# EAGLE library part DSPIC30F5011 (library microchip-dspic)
dsPIC General DSP with CAN and I2S ports
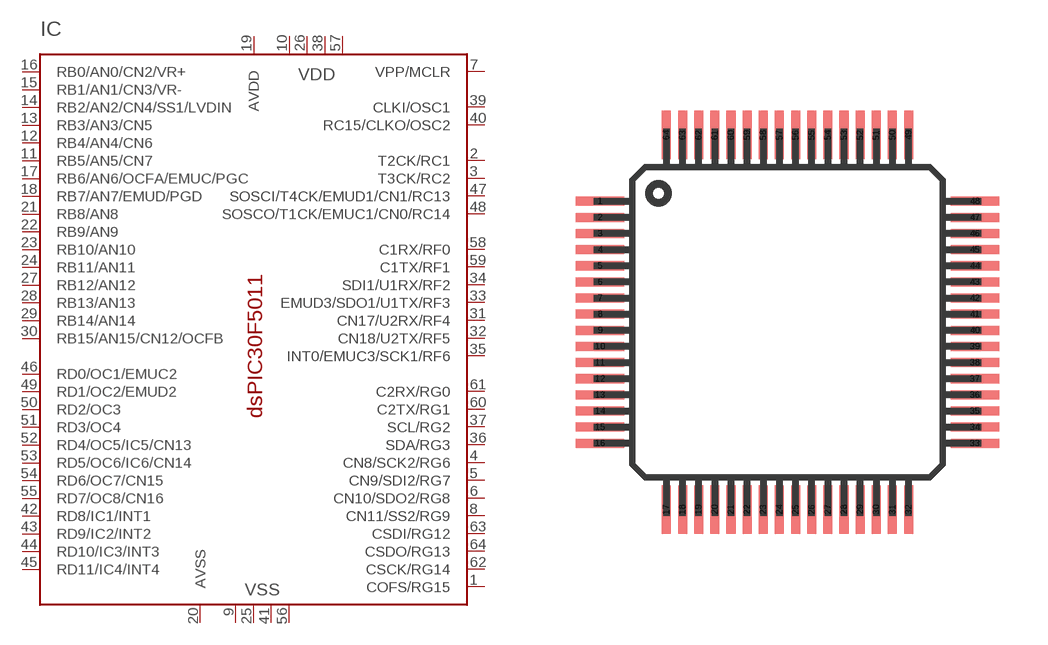
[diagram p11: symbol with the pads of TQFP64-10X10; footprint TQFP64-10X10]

Designator prefix IC

## DSPIC30F5011/PTG  [TQFP64-10X10]
1  COFS/RG15
2  T2CK/RC1
3  T3CK/RC2
4  CN8/SCK2/RG6
5  CN9/SDI2/RG7
6  CN10/SDO2/RG8
7  VPP/MCLR  in
8  CN11/SS2/RG9
9  VSS  pwr
10  VDD  pwr
11  RB5/AN5/CN7
12  RB4/AN4/CN6
13  RB3/AN3/CN5
14  RB2/AN2/CN4/SS1/LVDIN
15  RB1/AN1/CN3/VR-
16  RB0/AN0/CN2/VR+
17  RB6/AN6/OCFA/EMUC/PGC
18  RB7/AN7/EMUD/PGD
19  AVDD  pwr
20  AVSS  pwr
21  RB8/AN8
22  RB9/AN9
23  RB10/AN10
24  RB11/AN11
25  VSS  pwr
26  VDD  pwr
27  RB12/AN12
28  RB13/AN13
29  RB14/AN14
30  RB15/AN15/CN12/OCFB
31  CN17/U2RX/RF4
32  CN18/U2TX/RF5
33  EMUD3/SDO1/U1TX/RF3
34  SDI1/U1RX/RF2
35  INT0/EMUC3/SCK1/RF6
36  SDA/RG3
37  SCL/RG2
38  VDD  pwr
39  CLKI/OSC1  in
40  RC15/CLKO/OSC2
41  VSS  pwr
42  RD8/IC1/INT1
43  RD9/IC2/INT2
44  RD10/IC3/INT3
45  RD11/IC4/INT4
46  RD0/OC1/EMUC2
47  SOSCI/T4CK/EMUD1/CN1/RC13
48  SOSCO/T1CK/EMUC1/CN0/RC14
49  RD1/OC2/EMUD2
50  RD2/OC3
51  RD3/OC4
52  RD4/OC5/IC5/CN13
53  RD5/OC6/IC6/CN14
54  RD6/OC7/CN15
55  RD7/OC8/CN16
56  VSS  pwr
57  VDD  pwr
58  C1RX/RF0
59  C1TX/RF1
60  C2TX/RG1
61  C2RX/RG0
62  CSCK/RG14
63  CSDI/RG12
64  CSDO/RG13

## Footprint TQFP64-10X10 (pad centres in mm)
Thin Quad Flat Pack package type TQ
smd 1.5 x 0.28: 1 -5.8,3.75; 2 -5.8,3.25; 3 -5.8,2.75; 4 -5.8,2.25; 5 -5.8,1.75; 6 -5.8,1.25; 7 -5.8,0.75; 8 -5.8,0.25; 9 -5.8,-0.25; 10 -5.8,-0.75; 11 -5.8,-1.25; 12 -5.8,-1.75; 13 -5.8,-2.25; 14 -5.8,-2.75; 15 -5.8,-3.25; 16 -5.8,-3.75; 33 5.8,-3.75; 34 5.8,-3.25; 35 5.8,-2.75; 36 5.8,-2.25; 37 5.8,-1.75; 38 5.8,-1.25; 39 5.8,-0.75; 40 5.8,-0.25; 41 5.8,0.25; 42 5.8,0.75; 43 5.8,1.25; 44 5.8,1.75; 45 5.8,2.25; 46 5.8,2.75; 47 5.8,3.25; 48 5.8,3.75
smd 0.28 x 1.5: 17 -3.75,-5.8; 18 -3.25,-5.8; 19 -2.75,-5.8; 20 -2.25,-5.8; 21 -1.75,-5.8; 22 -1.25,-5.8; 23 -0.75,-5.8; 24 -0.25,-5.8; 25 0.25,-5.8; 26 0.75,-5.8; 27 1.25,-5.8; 28 1.75,-5.8; 29 2.25,-5.8; 30 2.75,-5.8; 31 3.25,-5.8; 32 3.75,-5.8; 49 3.75,5.8; 50 3.25,5.8; 51 2.75,5.8; 52 2.25,5.8; 53 1.75,5.8; 54 1.25,5.8; 55 0.75,5.8; 56 0.25,5.8; 57 -0.25,5.8; 58 -0.75,5.8; 59 -1.25,5.8; 60 -1.75,5.8; 61 -2.25,5.8; 62 -2.75,5.8; 63 -3.25,5.8; 64 -3.75,5.8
